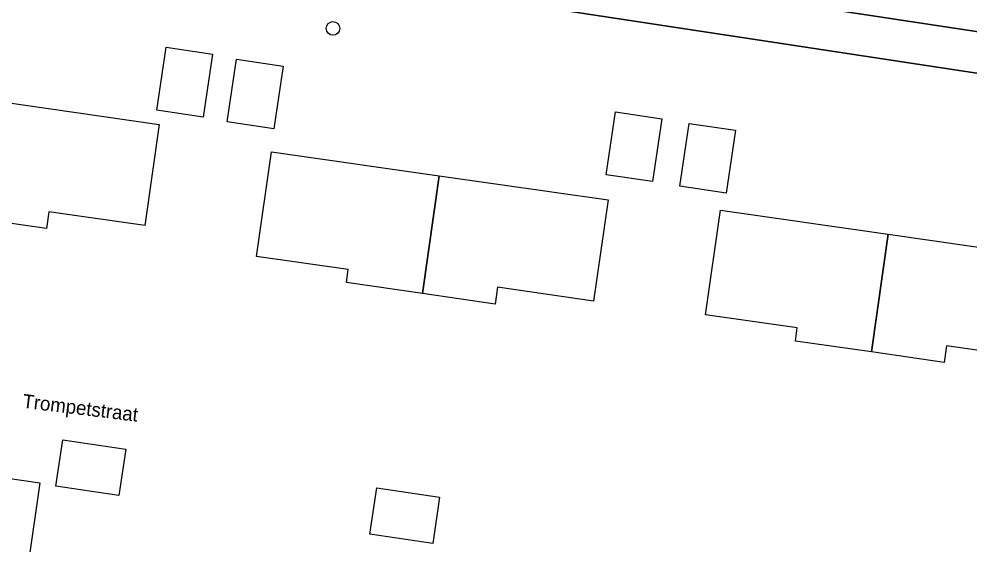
# Model space of a CAD drawing. Extents: x 164148 to 165261, y 382513 to 383432.
# Drawn here: x 164727.4 to 164795.6, y 382951.2 to 382989 of the extents above; entities that cross this region are included whole.
import ezdxf

# ---------------------------------------------------------------- set-up
doc = ezdxf.new("R2010")
doc.units = 0
for name, color, linetype in [('IMGEO_Boom', 7, 'Continuous'), ('IMGEO_Fietspad_gesloten', 7, 'Continuous'), ('IMGEO_Groenvoorziening', 7, 'Continuous'), ('IMGEO_Openbare_ruimte_label', 7, 'Continuous'), ('IMGEO_Pand_vergunning_verleend', 7, 'Continuous')]:
    doc.layers.add(name, color=color, linetype=linetype)

msp = doc.modelspace()

# ---------------------------------------------------------------- linework, layer by layer
at = {"layer": 'IMGEO_Boom'}
msp.add_circle((164749.959, 382988.288), 0.489, dxfattribs=at)
at = {"layer": 'IMGEO_Fietspad_gesloten'}
for points in [[(164659.708, 383008.804), (164659.275, 383005.882), (164764.64, 382989.85), (164848.685, 382977.103), (164852.653, 382976.484)], [(164853.349, 382979.402), (164849.159, 382980.044), (164765.127, 382992.769), (164659.708, 383008.804)]]:
    msp.add_lwpolyline(points, dxfattribs=at)
at = {"layer": 'IMGEO_Groenvoorziening'}
for points in [[(164659.708, 383008.804), (164765.127, 382992.769), (164849.159, 382980.044)], [(164852.653, 382976.484), (164848.685, 382977.103), (164764.64, 382989.85), (164659.275, 383005.882), (164658.504, 383000.69), (164650.933, 382950.305), (164641.67, 382887.255), (164640.801, 382881.34), (164637.731, 382860.442), (164636.909, 382854.849), (164636.824, 382854.453), (164636.636, 382853.576)]]:
    msp.add_lwpolyline(points, dxfattribs=at)
at = {"layer": 'IMGEO_Pand_vergunning_verleend'}
for points in [[(164737.318, 382982.432), (164737.989, 382986.938), (164741.324, 382986.441), (164740.653, 382981.935)], [(164742.38, 382981.583), (164743.051, 382986.089), (164746.386, 382985.593), (164745.715, 382981.087)], [(164724.189, 382974.683), (164725.401, 382983.132), (164737.505, 382981.396), (164736.464, 382974.144), (164729.588, 382975.13), (164729.416, 382973.933)], [(164769.536, 382977.794), (164770.207, 382982.3), (164773.542, 382981.804), (164772.871, 382977.298)], [(164774.817, 382976.973), (164775.488, 382981.479), (164778.823, 382980.983), (164778.152, 382976.476)], [(164744.483, 382971.938), (164745.559, 382979.444), (164757.578, 382977.72), (164756.366, 382969.271), (164750.922, 382970.052), (164751.057, 382970.995)], [(164756.366, 382969.271), (164757.578, 382977.72), (164769.682, 382975.983), (164768.641, 382968.731), (164761.765, 382969.718), (164761.593, 382968.521)], [(164776.675, 382967.747), (164777.752, 382975.253), (164789.77, 382973.529), (164788.558, 382965.08), (164783.114, 382965.861), (164783.249, 382966.804)], [(164788.558, 382965.08), (164789.77, 382973.529), (164801.874, 382971.792), (164800.833, 382964.54), (164793.957, 382965.527), (164793.785, 382964.33)], [(164730.096, 382955.453), (164730.593, 382958.788), (164735.099, 382958.117), (164734.603, 382954.782)], [(164718.031, 382951.138), (164718.899, 382957.145), (164728.94, 382955.695), (164728.073, 382949.688)], [(164752.601, 382952.004), (164753.098, 382955.339), (164757.604, 382954.669), (164757.107, 382951.333)]]:
    msp.add_lwpolyline(points, close=True, dxfattribs=at)

# ---------------------------------------------------------------- texts
at = {"layer": 'IMGEO_Openbare_ruimte_label'}
msp.add_text('Trompetstraat', height=1, rotation=353.05259, dxfattribs=at).set_placement((164727.653, 382961.082))

doc.saveas('drawing.dxf')
